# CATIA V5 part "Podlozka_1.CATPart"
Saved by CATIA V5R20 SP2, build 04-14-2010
Part number: Part1
Bounding box of the stored display mesh (mm): x -4.999 to 4.999, y -4.999 to 4.999, z 0 to 3
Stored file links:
  C:\Documents and Settings\Administrator\My Documents\Hobi_dokumenti\CAD_CNC\Clap_CATIA\Podlozka_1.CATPart
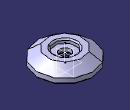
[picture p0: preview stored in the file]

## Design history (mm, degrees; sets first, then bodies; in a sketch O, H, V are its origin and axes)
StDynAnalysisRootNodeFeature1 "CATStDynAnalysisRootNodeName"
Set1
  Line1: type PtDir, RefPoint Sketch1.O, Direction Sketch1.V, Start 0, End 3
Body1 (main body)
  Sketch1 on yz-plane, origin (0, 0, 0), H (0, 1, 0), V (0, 0, 1)
    point P1 (-2, 0)
    line L1 (-2, 0) -> (-5, 0)
    line L2 (-5, 0) -> (-5, 1)
    line L3 (-2, 1) -> (-2, 0)
    point P3 (-5, 1)
    point P4 (-2, 1)
    line L4 (-2, 1) -> (-1, 1)
    point P5 (-1, 1)
    line L5 (-1, 1) -> (-1, 1.6)
    point P6 (-1, 1.6)
    line L6 (-1, 1.6) -> (-2, 1.6)
    point P7 (-2, 1.6)
    line L7 (-2, 1.6) -> (-2, 2.3)
    point P8 (-2, 2.3)
    line L8 (-2, 2.3) -> (-3.2, 2.3)
    point P9 (-3.2, 2.3)
    line L9 (-5, 1) -> (-3.2, 2.3)
    reference intersected line E1 through (0, 0) direction (-1, 0) from xy-plane
    reference intersected line E3 through (0, 0) direction (0, 1) from zx-plane
    distance V L2 = 5
    distance V L3 = 2
    distance P8 P9 = 1.2
    distance P5 P6 = 0.6
    distance P7 P8 = 0.7
    distance P6 P7 = 1
    distance P4 P1 = 1
    distance V L5 = 1
    coincidence: P1 H, P3 L4
    horizontal: L1 H, L4 H, L6 H, L8 H, E1 H
    vertical: L2 V, L3 V, L5 V, L7 V, E3 V
    perpendicularity: E1 L5
  Shaft1: profile Sketch1, axis Line1, angle 360
  Chamfer1: length 0.2, angle 45, on edge [face of Shaft1 from Sketch1.L1 | face of Shaft1 from Sketch1.L2]; edge [face of Shaft1 from Sketch1.L3 | face of Shaft1 from Sketch1.L1]; edge [face of Shaft1 from Sketch1.L8 | face of Shaft1 from Sketch1.L7]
